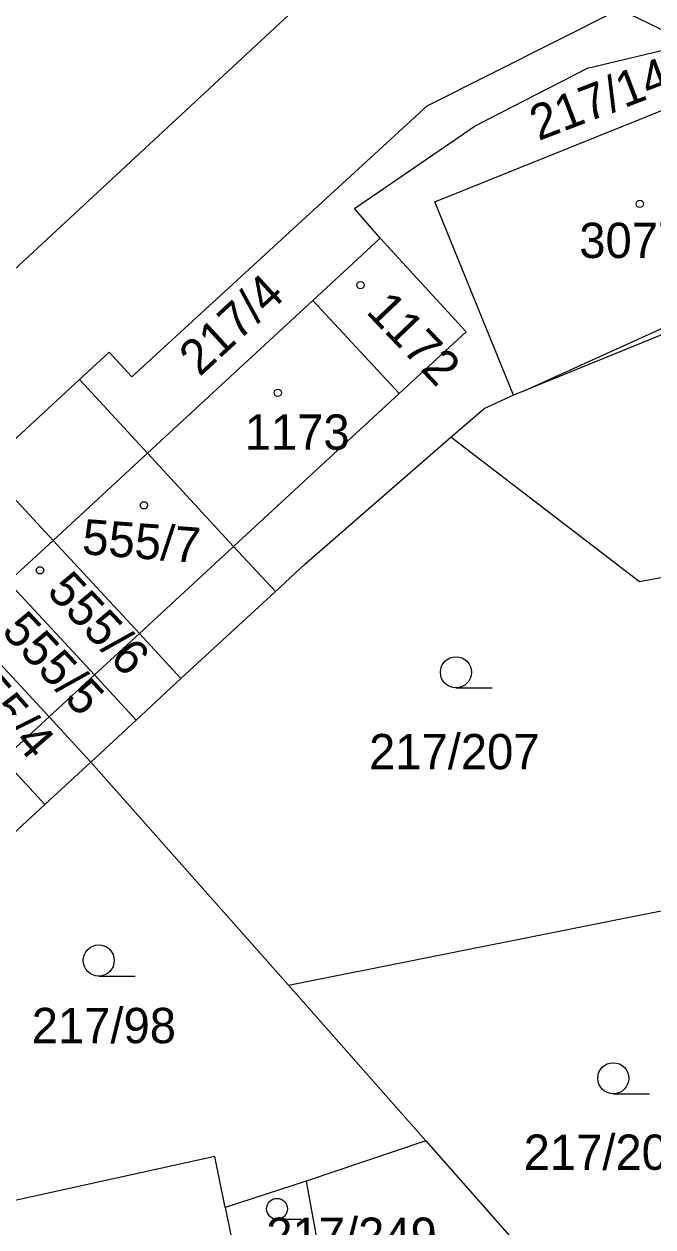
# Model space of a CAD drawing. Extents: x -735249 to -729401, y -1124843 to -1121828.
# Drawn here: x -733217.9 to -733187.6, y -1123229.8 to -1123171.8 of the extents above; entities that cross this region are included whole.
import ezdxf

# ---------------------------------------------------------------- set-up
doc = ezdxf.new("R2010")
doc.units = 0
for name, color, linetype in [('Vrstva 1', 7, 'Continuous'), ('Vrstva 18', 7, 'Continuous'), ('Vrstva 19', 7, 'Continuous'), ('Vrstva 25', 7, 'Continuous'), ('Vrstva 4', 7, 'Continuous')]:
    doc.layers.add(name, color=color, linetype=linetype)

msp = doc.modelspace()

# ---------------------------------------------------------------- linework, layer by layer
at = {"layer": 'Vrstva 1'}
for points in [[(-733218.39, -1123183.67), (-733199.56, -1123166.18)], [(-733198.49, -1123175.77), (-733189.22, -1123171.11)], [(-733189.22, -1123171.11), (-733185.59, -1123172.86)], [(-733190.76, -1123173.96), (-733186.19, -1123172.86)], [(-733198.12, -1123180.4), (-733181.48, -1123173.7)], [(-733196.18, -1123176.74), (-733190.76, -1123173.96)], [(-733212.72, -1123188.82), (-733198.49, -1123175.77)], [(-733201.99, -1123180.72), (-733196.18, -1123176.74)], [(-733193.82, -1123189.49), (-733171.92, -1123179.57)], [(-733194.33, -1123189.7), (-733198.12, -1123180.4)], [(-733200.75, -1123182.15), (-733201.99, -1123180.72)], [(-733172.16, -1123180.68), (-733193.82, -1123189.49)], [(-733204, -1123185.15), (-733200.75, -1123182.15)], [(-733200.75, -1123182.15), (-733196.61, -1123186.65)], [(-733211.96, -1123192.5), (-733204, -1123185.15)], [(-733204, -1123185.15), (-733199.84, -1123189.63)], [(-733196.61, -1123186.65), (-733199.84, -1123189.63)], [(-733215.24, -1123188.95), (-733213.81, -1123187.63)], [(-733213.81, -1123187.63), (-733212.72, -1123188.82)], [(-733219.79, -1123193.15), (-733215.24, -1123188.95)], [(-733215.24, -1123188.95), (-733211.96, -1123192.5)], [(-733199.84, -1123189.63), (-733207.81, -1123196.99)], [(-733194.33, -1123189.7), (-733195.75, -1123190.36)], [(-733193.82, -1123189.49), (-733194.33, -1123189.7)], [(-733197.35, -1123191.72), (-733195.75, -1123190.36)], [(-733204.39, -1123197.86), (-733197.35, -1123191.72)], [(-733188.26, -1123198.7), (-733197.35, -1123191.72)], [(-733211.96, -1123192.5), (-733207.81, -1123196.99)], [(-733219.79, -1123193.15), (-733216.51, -1123196.7)], [(-733216.51, -1123196.7), (-733212.35, -1123201.18)], [(-733207.81, -1123196.99), (-733205.8, -1123199.16)], [(-733178.53, -1123196.86), (-733188.26, -1123198.7)], [(-733205.8, -1123199.16), (-733204.39, -1123197.86)], [(-733218.67, -1123198.69), (-733214.51, -1123203.18)], [(-733205.8, -1123199.16), (-733210.35, -1123203.35)], [(-733220.85, -1123200.71), (-733216.7, -1123205.2)], [(-733212.35, -1123201.18), (-733210.35, -1123203.35)], [(-733214.51, -1123203.18), (-733212.51, -1123205.35)], [(-733210.35, -1123203.35), (-733212.51, -1123205.35)], [(-733216.7, -1123205.2), (-733214.69, -1123207.37)], [(-733212.51, -1123205.35), (-733214.69, -1123207.37)], [(-733218.91, -1123207.24), (-733216.91, -1123209.41)], [(-733214.69, -1123207.37), (-733216.91, -1123209.41)], [(-733205.17, -1123218.11), (-733214.69, -1123207.37)], [(-733216.91, -1123209.41), (-733219.11, -1123211.44)], [(-733205.17, -1123218.11), (-733185.13, -1123214.12)], [(-733205.17, -1123218.11), (-733198.55, -1123225.62)], [(-733198.55, -1123225.62), (-733204.31, -1123227.55)], [(-733198.55, -1123225.62), (-733186.77, -1123238.99)], [(-733208.72, -1123226.36), (-733221.93, -1123229.27)], [(-733208.22, -1123228.82), (-733208.72, -1123226.36)], [(-733204.31, -1123227.55), (-733208.22, -1123228.82)], [(-733204.31, -1123227.55), (-733200.01, -1123251.17)], [(-733208.22, -1123228.82), (-733207.91, -1123230.3)]]:
    msp.add_lwpolyline(points, dxfattribs=at)
at = {"layer": 'Vrstva 25'}
for points in [[(-733197.1, -1123203.8), (-733195.35, -1123203.8)], [(-733214.31, -1123217.68), (-733212.56, -1123217.68)], [(-733189.52, -1123223.35), (-733187.77, -1123223.35)], [(-733205.72, -1123229.39), (-733204.547, -1123229.39)]]:
    msp.add_lwpolyline(points, dxfattribs=at)
for centre, radius in [((-733188.24, -1123180.49), 0.175), ((-733201.7, -1123184.41), 0.175), ((-733205.68, -1123189.59), 0.175), ((-733212.13, -1123195.01), 0.175), ((-733217.14, -1123198.14), 0.175), ((-733197.1, -1123203.05), 0.75), ((-733214.31, -1123216.93), 0.75), ((-733189.52, -1123222.6), 0.75), ((-733205.72, -1123228.887), 0.503)]:
    msp.add_circle(centre, radius, dxfattribs=at)
at = {"layer": 'Vrstva 4'}
for points in [[(-733216.51, -1123196.7), (-733211.96, -1123192.5)], [(-733218.67, -1123198.69), (-733216.51, -1123196.7)], [(-733207.81, -1123196.99), (-733212.35, -1123201.18)], [(-733212.35, -1123201.18), (-733214.51, -1123203.18)], [(-733214.51, -1123203.18), (-733216.7, -1123205.2)], [(-733216.7, -1123205.2), (-733218.91, -1123207.24)]]:
    msp.add_lwpolyline(points, dxfattribs=at)

# ---------------------------------------------------------------- texts
at = {"layer": 'Vrstva 18'}
for s, rotation, p in [('217/141', 21.00017, (-733193.125, -1123177.472)), ('217/4', 42.70034, (-733209.449, -1123188.848))]:
    msp.add_text(s, height=1.7, rotation=rotation, dxfattribs=at).set_placement(p)
for s, p in [('217/207', (-733201.29, -1123207.72)), ('217/98', (-733217.54, -1123220.91)), ('217/208', (-733193.84, -1123227.01)), ('217/249', (-733206.24, -1123231.01))]:
    msp.add_text(s, height=1.7, dxfattribs=at).set_placement(p)
at = {"layer": 'Vrstva 19'}
for s, p in [('3077/1', (-733191.16, -1123183.1)), ('1173', (-733207.28, -1123192.33))]:
    msp.add_text(s, height=1.7, dxfattribs=at).set_placement(p)
for s, rotation, p in [('1172', 313.60249, (-733201.478, -1123185.716)), ('555/7', 355.60283, (-733215.146, -1123197.356)), ('555/6', 313.30249, (-733216.868, -1123199.198)), ('555/5', 313.20249, (-733219.048, -1123201.118)), ('555/4', 310.80247, (-733221.318, -1123203.05))]:
    msp.add_text(s, height=1.7, rotation=rotation, dxfattribs=at).set_placement(p)

doc.saveas('drawing.dxf')
